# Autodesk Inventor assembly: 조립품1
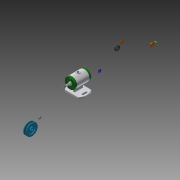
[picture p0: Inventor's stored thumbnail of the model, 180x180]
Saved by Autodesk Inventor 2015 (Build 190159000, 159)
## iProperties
Created: 2021-09
Part Number: 조립품1
Document SubType Name: Assembly
Designer: now
Author: now
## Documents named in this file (14)
- C:\Users\now\Desktop\710906V1008\조립품1.iam
- C:\Users\now\Desktop\710906V1008\V벨트풀리.ipt
- C:\Users\now\Desktop\710906V1008\너트 M8.ipt
- C:\Users\now\Desktop\710906V1008\뒤커버.ipt
- C:\Users\now\Desktop\710906V1008\베어링 15x32x9.ipt
- C:\Users\now\Desktop\710906V1008\본체.ipt
- C:\Users\now\Desktop\710906V1008\볼트 M4x12.ipt
- C:\Users\now\Desktop\710906V1008\스프링와셔 8.ipt
- C:\Users\now\Desktop\710906V1008\앞커버.ipt
- C:\Users\now\Desktop\710906V1008\오일 실 15x25x7.ipt
- C:\Users\now\Desktop\710906V1008\와셔 8x17.ipt
- C:\Users\now\Desktop\710906V1008\축.ipt
- C:\Users\now\Desktop\710906V1008\캡.ipt
- C:\Users\now\Desktop\710906V1008\키 3x3.ipt
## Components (1 placed, 1 different names)
1. V벨트풀리:1
